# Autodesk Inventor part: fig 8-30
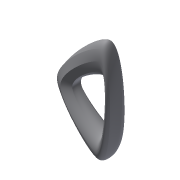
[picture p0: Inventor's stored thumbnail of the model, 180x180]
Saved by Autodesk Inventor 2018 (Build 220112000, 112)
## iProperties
Created: 2008-06
Part Number: fig 8-30
Document SubType Name: Modeling
Designer: CADCIM
Density: 1 g/cm^3
Material: Generic
Appearance: Default
Author: CADCIM
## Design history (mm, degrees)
sketch "Sketch1"
  geometry: L1 (-0.077, 5.773)-(4.961, 2.953); L2 (4.961, 2.953)-(5.038, -2.82); L3 (5.038, -2.82)-(0.077, -5.773); L4 (0.077, -5.773)-(-4.961, -2.953); L5 (-4.961, -2.953)-(-5.038, 2.82); L6 (-5.038, 2.82)-(-0.077, 5.773); 1 further point
  constraints: 12 end point, 13 other
  dimensions: "d0" = 10 distance between parallel lines of L2 L5
workplane "Work Plane1"
sketch "Sketch2"
  geometry: C1 r 7.5 at (-0.159, -25); 1 further point
  constraints: 1 centre point
  dimensions: "d2" = 15 diameter of C1; "d3" = 25 vertical distance of C1.centre point (0, 0)
sketch "Sketch3" dims "d4" = 10, "d5" = 5
  geometry: 2 further points; 1 other entity
  constraints: 2 other
  dimensions: "d6" = 25 vertical distance of point (0.175, 25) point (0, 0)
loft "Loft1" sketch "Sketch2", "Sketch3" dims "d7" = 0, "d8" = 90 deg, "d9" = 0, "d10" = 90 deg, "d11" = 0, "d12" = 90 deg
body "Solid1"
other parameters: "d1" = 25
